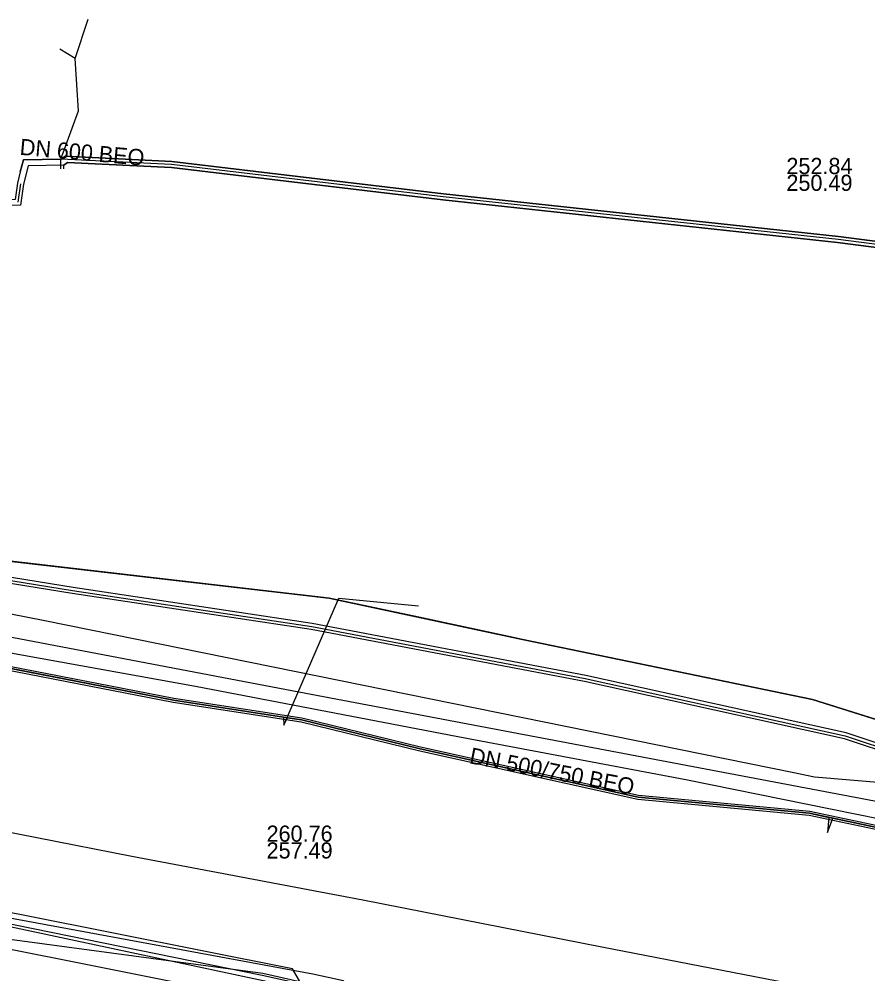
# Model space of a CAD drawing. Extents: x -599951 to -598963, y -1164095 to -1162939.
# Drawn here: x -599823.08 to -599781.05, y -1163059.74 to -1163012.43 of the extents above; entities that cross this region are included whole.
import ezdxf

# ---------------------------------------------------------------- set-up
doc = ezdxf.new("R2010")
doc.units = 0
for name, color, linetype in [('Vrstva 12', 7, 'Continuous'), ('Vrstva 19', 7, 'Continuous'), ('Vrstva 20', 7, 'Continuous'), ('Vrstva 42', 7, 'Continuous'), ('Vrstva 44', 7, 'Continuous'), ('Vrstva 50', 7, 'Continuous'), ('Vrstva 55', 7, 'Continuous'), ('Vrstva 58', 7, 'Continuous')]:
    doc.layers.add(name, color=color, linetype=linetype)

msp = doc.modelspace()

# ---------------------------------------------------------------- linework, layer by layer
at = {"layer": 'Vrstva 12'}
for p, q in [((-599821.8, -1163042.25), (-599823.57, -1163041.9)), ((-599784.71, -1163049.77), (-599821.8, -1163042.25))]:
    msp.add_line(p, q, dxfattribs=at)
for points in [[(-599778.4, -1163050.43), (-599783.7, -1163049.99), (-599784.71, -1163049.77)], [(-599808.4, -1163075.41), (-599806.05, -1163063.47), (-599805.96, -1163062.96), (-599805.85, -1163062.25), (-599805.95, -1163061.63), (-599806.18, -1163061.15), (-599806.36, -1163060.78), (-599806.57, -1163060.51), (-599807.02, -1163060.09), (-599808.54, -1163059.75), (-599841.96, -1163053.57), (-599846.49, -1163052.73)]]:
    msp.add_lwpolyline(points, dxfattribs=at)
at = {"layer": 'Vrstva 19'}
msp.add_lwpolyline([(-599741.561, -1163083.741), (-599749.337, -1163082.368), (-599759.986, -1163080.568), (-599773.585, -1163078.162), (-599785.969, -1163075.634), (-599789.812, -1163076.062), (-599794.62, -1163074.71), (-599796.63, -1163073), (-599800.62, -1163069), (-599804.87, -1163064.7), (-599807.8, -1163061.67), (-599826.41, -1163057.95), (-599839.25, -1163055.38), (-599857.71, -1163051.77), (-599869.416, -1163053.613), (-599869.995, -1163053.663), (-599872.225, -1163054.024), (-599874.316, -1163053.849), (-599875.409, -1163053.774)], dxfattribs=at)
at = {"layer": 'Vrstva 20'}
msp.add_lwpolyline([(-599883.05, -1163052.54), (-599873.56, -1163051.94), (-599873.14, -1163051.47), (-599872.98, -1163049.36), (-599872.6, -1163047.57), (-599869.57, -1163036.17), (-599869.08, -1163035.73), (-599867.99, -1163036.09), (-599863.42, -1163036.97), (-599853.5, -1163038.54), (-599849.37, -1163039.34), (-599847.49, -1163039.61), (-599846.18, -1163040.18), (-599841.31, -1163041.11), (-599828.6, -1163043.61), (-599815.43, -1163046.17), (-599809.1, -1163047.15), (-599803.22, -1163048.59), (-599792.42, -1163050.98), (-599783.94, -1163051.78), (-599774.84, -1163053.7), (-599762.66, -1163055.93), (-599749, -1163058.61), (-599740.93, -1163058.73)], dxfattribs=at)
at = {"layer": 'Vrstva 42'}
for p, q in [((-599826.206, -1163038.978), (-599807.734, -1163041.119)), ((-599826.206, -1163038.978), (-599807.734, -1163041.119)), ((-599807.734, -1163041.119), (-599798.148, -1163043.163)), ((-599807.734, -1163041.119), (-599798.148, -1163043.163)), ((-599798.148, -1163043.163), (-599783.799, -1163046.138)), ((-599798.148, -1163043.163), (-599783.799, -1163046.138)), ((-599783.799, -1163046.138), (-599778.116, -1163047.934)), ((-599783.799, -1163046.138), (-599778.116, -1163047.934))]:
    msp.add_line(p, q, dxfattribs=at)
for points in [[(-599821.016, -1163019.854), (-599821.01, -1163019.37), (-599820.142, -1163016.97), (-599820.3, -1163014.39), (-599819.661, -1163012.431)], [(-599821.016, -1163019.854), (-599821.01, -1163019.37), (-599820.142, -1163016.97), (-599820.3, -1163014.39), (-599819.661, -1163012.431)], [(-599823.02, -1163019.991), (-599822.87, -1163019.4), (-599821.01, -1163019.37), (-599820.142, -1163016.97), (-599820.3, -1163014.39), (-599821.07, -1163013.92)], [(-599823.02, -1163019.991), (-599822.87, -1163019.4), (-599821.01, -1163019.37), (-599820.142, -1163016.97), (-599820.3, -1163014.39), (-599821.07, -1163013.92)], [(-599815.518, -1163019.48), (-599820.791, -1163019.23), (-599821.01, -1163019.37), (-599822.87, -1163019.4), (-599823.02, -1163019.991), (-599823.159, -1163020.568), (-599823.271, -1163021.364), (-599827.714, -1163021.51), (-599835.493, -1163022.702), (-599852.557, -1163025.328), (-599854.173, -1163026.768), (-599855.063, -1163030.103), (-599854.618, -1163032.62), (-599851.529, -1163035.218), (-599847.993, -1163036.016), (-599847.84, -1163036.05), (-599848.693, -1163040.788), (-599851.012, -1163052.737), (-599851.441, -1163055.21), (-599851.947, -1163060.521), (-599893.107, -1163090.941)], [(-599815.518, -1163019.48), (-599820.791, -1163019.23), (-599821.01, -1163019.37), (-599822.87, -1163019.4), (-599823.02, -1163019.991), (-599823.159, -1163020.568), (-599823.271, -1163021.364), (-599827.714, -1163021.51), (-599835.493, -1163022.702), (-599852.557, -1163025.328), (-599854.173, -1163026.768), (-599855.063, -1163030.103), (-599854.618, -1163032.62), (-599851.529, -1163035.218), (-599847.993, -1163036.016), (-599847.84, -1163036.05), (-599848.693, -1163040.788), (-599851.012, -1163052.737), (-599851.441, -1163055.21), (-599851.947, -1163060.521), (-599893.107, -1163090.941)], [(-599735.209, -1163031.191), (-599748.973, -1163028.922), (-599754.582, -1163027.773), (-599763.609, -1163026.245), (-599763.605, -1163026.246), (-599764.382, -1163026.091), (-599764.757, -1163025.994), (-599772.386, -1163024.512), (-599782.512, -1163023.201), (-599802.063, -1163021.081), (-599815.518, -1163019.48), (-599820.791, -1163019.23), (-599821.01, -1163019.37), (-599822.87, -1163019.4), (-599823.02, -1163019.991), (-599823.159, -1163020.568)], [(-599735.209, -1163031.191), (-599748.973, -1163028.922), (-599754.582, -1163027.773), (-599763.609, -1163026.245), (-599763.605, -1163026.246), (-599764.382, -1163026.091), (-599764.757, -1163025.994), (-599772.386, -1163024.512), (-599782.512, -1163023.201), (-599802.063, -1163021.081), (-599815.518, -1163019.48), (-599820.791, -1163019.23), (-599821.01, -1163019.37), (-599822.87, -1163019.4), (-599823.02, -1163019.991), (-599823.159, -1163020.568)], [(-599823.02, -1163019.991), (-599822.87, -1163019.4), (-599821.01, -1163019.37), (-599820.791, -1163019.23), (-599815.518, -1163019.48), (-599802.063, -1163021.081), (-599782.512, -1163023.201), (-599772.386, -1163024.512), (-599764.757, -1163025.994), (-599764.382, -1163026.091), (-599763.605, -1163026.246), (-599763.609, -1163026.245), (-599754.582, -1163027.773), (-599748.973, -1163028.922), (-599735.209, -1163031.191)], [(-599823.02, -1163019.991), (-599822.87, -1163019.4), (-599821.01, -1163019.37), (-599820.791, -1163019.23), (-599815.518, -1163019.48), (-599802.063, -1163021.081), (-599782.512, -1163023.201), (-599772.386, -1163024.512), (-599764.757, -1163025.994), (-599764.382, -1163026.091), (-599763.605, -1163026.246), (-599763.609, -1163026.245), (-599754.582, -1163027.773), (-599748.973, -1163028.922), (-599735.209, -1163031.191)], [(-599735.209, -1163031.191), (-599748.973, -1163028.922), (-599754.582, -1163027.773), (-599763.609, -1163026.245), (-599763.605, -1163026.246), (-599764.382, -1163026.091), (-599764.757, -1163025.994), (-599772.386, -1163024.512), (-599782.512, -1163023.201), (-599802.063, -1163021.081), (-599815.518, -1163019.48), (-599820.791, -1163019.23), (-599821.01, -1163019.37), (-599822.87, -1163019.4), (-599823.02, -1163019.991)], [(-599823.02, -1163019.991), (-599822.87, -1163019.4), (-599821.01, -1163019.37), (-599820.791, -1163019.23), (-599815.518, -1163019.48), (-599802.063, -1163021.081), (-599782.512, -1163023.201), (-599772.386, -1163024.512), (-599764.757, -1163025.994), (-599764.382, -1163026.091), (-599763.605, -1163026.246), (-599763.609, -1163026.245), (-599754.582, -1163027.773), (-599748.973, -1163028.922), (-599735.209, -1163031.191)], [(-599821.01, -1163019.37), (-599822.87, -1163019.4), (-599823.02, -1163019.991)], [(-599763.634, -1163026.393), (-599764.416, -1163026.237), (-599764.79, -1163026.14), (-599772.41, -1163024.66), (-599782.53, -1163023.35), (-599802.08, -1163021.23), (-599815.53, -1163019.63), (-599821.01, -1163019.37)], [(-599735.259, -1163031.487), (-599749.027, -1163029.218), (-599754.638, -1163028.067), (-599763.659, -1163026.541), (-599763.663, -1163026.54), (-599764.45, -1163026.383), (-599764.823, -1163026.286), (-599772.434, -1163024.808), (-599782.548, -1163023.499), (-599802.097, -1163021.379), (-599815.542, -1163019.78), (-599820.691, -1163019.536), (-599820.864, -1163019.668), (-599822.636, -1163019.696), (-599822.861, -1163020.61), (-599823.009, -1163021.656), (-599827.686, -1163021.81)], [(-599735.259, -1163031.487), (-599749.027, -1163029.218), (-599754.638, -1163028.067), (-599763.659, -1163026.541), (-599763.663, -1163026.54), (-599764.45, -1163026.383), (-599764.823, -1163026.286), (-599772.434, -1163024.808), (-599782.548, -1163023.499), (-599802.097, -1163021.379), (-599815.542, -1163019.78), (-599820.691, -1163019.536), (-599820.864, -1163019.668), (-599822.636, -1163019.696), (-599822.861, -1163020.61), (-599823.009, -1163021.656), (-599827.686, -1163021.81)], [(-599820.866, -1163019.856), (-599820.864, -1163019.668), (-599820.691, -1163019.536), (-599815.542, -1163019.78), (-599802.097, -1163021.379), (-599782.548, -1163023.499), (-599772.434, -1163024.808), (-599764.823, -1163026.286), (-599764.45, -1163026.383), (-599763.663, -1163026.54), (-599763.659, -1163026.541), (-599754.638, -1163028.067), (-599749.027, -1163029.218), (-599735.259, -1163031.487)], [(-599820.866, -1163019.856), (-599820.864, -1163019.668), (-599820.691, -1163019.536), (-599815.542, -1163019.78), (-599802.097, -1163021.379), (-599782.548, -1163023.499), (-599772.434, -1163024.808), (-599764.823, -1163026.286), (-599764.45, -1163026.383), (-599763.663, -1163026.54), (-599763.659, -1163026.541), (-599754.638, -1163028.067), (-599749.027, -1163029.218), (-599735.259, -1163031.487)], [(-599735.209, -1163031.191), (-599748.973, -1163028.922), (-599754.582, -1163027.773), (-599763.609, -1163026.245), (-599763.605, -1163026.246), (-599764.382, -1163026.091), (-599764.757, -1163025.994), (-599772.386, -1163024.512), (-599782.512, -1163023.201), (-599802.063, -1163021.081), (-599815.518, -1163019.48)], [(-599735.209, -1163031.191), (-599748.973, -1163028.922), (-599754.582, -1163027.773), (-599763.609, -1163026.245), (-599763.605, -1163026.246), (-599764.382, -1163026.091), (-599764.757, -1163025.994), (-599772.386, -1163024.512), (-599782.512, -1163023.201), (-599802.063, -1163021.081), (-599815.518, -1163019.48)], [(-599823.01, -1163020.589), (-599823.14, -1163021.51)], [(-599736.94, -1163069.5), (-599747.67, -1163067.47), (-599759.18, -1163065.22), (-599771.56, -1163062.81), (-599782.31, -1163060.73), (-599794.22, -1163058.42), (-599806.06, -1163056.09), (-599817.5, -1163053.92), (-599826.93, -1163052.08), (-599837.11, -1163050.1), (-599848.95, -1163047.79), (-599860.32, -1163045.57), (-599870.33, -1163043.62), (-599881.88, -1163041.35), (-599892.48, -1163039.26), (-599902.25, -1163037.36), (-599911.67, -1163035.55), (-599921.63, -1163033.57), (-599932.53, -1163031.46), (-599941.74, -1163029.67), (-599951.125, -1163027.795)], [(-599742.215, -1163055.552), (-599755.449, -1163053.841), (-599771.375, -1163051.364), (-599782.13, -1163047.795), (-599795.02, -1163044.953), (-599808.565, -1163042.372), (-599820.407, -1163040.592), (-599840.692, -1163037.303), (-599847.928, -1163035.723), (-599848.08, -1163035.69), (-599848.987, -1163040.732), (-599851.308, -1163052.683), (-599851.739, -1163055.17), (-599852.233, -1163060.359), (-599893.313, -1163090.719), (-599898.373, -1163096.584), (-599905.793, -1163118.694), (-599909.483, -1163130.424), (-599919.431, -1163160.679), (-599923.942, -1163172.071), (-599928.754, -1163188.287), (-599951.125, -1163246.248)], [(-599742.215, -1163055.552), (-599755.449, -1163053.841), (-599771.375, -1163051.364), (-599782.13, -1163047.795), (-599795.02, -1163044.953), (-599808.565, -1163042.372), (-599820.407, -1163040.592), (-599840.692, -1163037.303), (-599847.928, -1163035.723), (-599848.08, -1163035.69), (-599848.987, -1163040.732), (-599851.308, -1163052.683), (-599851.739, -1163055.17), (-599852.233, -1163060.359), (-599893.313, -1163090.719), (-599898.373, -1163096.584), (-599905.793, -1163118.694), (-599909.483, -1163130.424), (-599919.431, -1163160.679), (-599923.942, -1163172.071), (-599928.754, -1163188.287), (-599951.125, -1163246.248)], [(-599847.96, -1163035.87), (-599840.72, -1163037.45), (-599820.43, -1163040.74), (-599808.59, -1163042.52), (-599795.05, -1163045.1), (-599782.17, -1163047.94), (-599771.41, -1163051.51), (-599755.47, -1163053.99), (-599742.24, -1163055.7), (-599730.83, -1163058.1), (-599723.97, -1163059.15), (-599715.25, -1163060.7), (-599698.74, -1163063.9), (-599666.16, -1163068.57), (-599655.17, -1163067.91), (-599647.96, -1163067.11), (-599641.24, -1163065.92), (-599633.17, -1163063.6), (-599622.92, -1163059.72), (-599616.64, -1163055.22), (-599609.94, -1163050.49)], [(-599742.265, -1163055.848), (-599755.491, -1163054.139), (-599771.445, -1163051.656), (-599782.21, -1163048.085), (-599795.08, -1163045.247), (-599808.615, -1163042.668), (-599820.453, -1163040.888), (-599840.748, -1163037.597), (-599847.84, -1163036.05), (-599848.693, -1163040.788), (-599851.012, -1163052.737), (-599851.441, -1163055.21), (-599851.947, -1163060.521), (-599893.107, -1163090.941), (-599898.107, -1163096.736), (-599905.507, -1163118.786), (-599909.197, -1163130.516), (-599919.149, -1163160.781), (-599923.658, -1163172.169), (-599928.466, -1163188.373), (-599951.125, -1163247.074)], [(-599742.265, -1163055.848), (-599755.491, -1163054.139), (-599771.445, -1163051.656), (-599782.21, -1163048.085), (-599795.08, -1163045.247), (-599808.615, -1163042.668), (-599820.453, -1163040.888), (-599840.748, -1163037.597), (-599847.84, -1163036.05), (-599848.693, -1163040.788), (-599851.012, -1163052.737), (-599851.441, -1163055.21), (-599851.947, -1163060.521), (-599893.107, -1163090.941), (-599898.107, -1163096.736), (-599905.507, -1163118.786), (-599909.197, -1163130.516), (-599919.149, -1163160.781), (-599923.658, -1163172.169), (-599928.466, -1163188.373), (-599951.125, -1163247.074)], [(-599790.25, -1163100.41), (-599791.97, -1163097.44), (-599790.35, -1163085.48), (-599790.7, -1163085.03), (-599800.21, -1163083.2), (-599802.06, -1163082.74), (-599802.3, -1163082.3), (-599802.03, -1163079.98), (-599800.42, -1163070.73), (-599800.55, -1163070.2), (-599806.83, -1163069.05), (-599807.31, -1163068.48), (-599807.69, -1163063.21), (-599807.82, -1163062.44), (-599809.55, -1163059.49), (-599822.79, -1163056.85), (-599830.99, -1163055.24)]]:
    msp.add_lwpolyline(points, dxfattribs=at)
at = {"layer": 'Vrstva 44'}
msp.add_lwpolyline([(-599951.125, -1163018.319), (-599947.551, -1163019.333), (-599942.738, -1163020.646), (-599932.806, -1163022.793), (-599910.515, -1163027.389), (-599898.233, -1163029.739), (-599885.727, -1163032.363), (-599873.009, -1163034.84), (-599861.264, -1163036.995), (-599853.19, -1163038.533), (-599847.084, -1163039.492), (-599839.909, -1163041.111), (-599824.895, -1163043.577), (-599814.349, -1163045.484), (-599801.363, -1163047.973), (-599790.063, -1163050.107), (-599778.01, -1163052.554), (-599760.155, -1163055.725), (-599748.035, -1163058.372), (-599724.432, -1163062.801)], dxfattribs=at)
at = {"layer": 'Vrstva 50'}
msp.add_lwpolyline([(-599740.93, -1163058.73), (-599749, -1163058.61), (-599762.66, -1163055.93), (-599774.84, -1163053.7), (-599782.792, -1163052.031), (-599783.94, -1163051.78), (-599792.42, -1163050.98), (-599803.22, -1163048.59), (-599809.1, -1163047.15), (-599809.988, -1163047.015), (-599815.43, -1163046.17), (-599843.958, -1163040.613)], dxfattribs=at)
at = {"layer": 'Vrstva 55'}
for points in [[(-599664.02, -1163109.18), (-599663.75, -1163108.82), (-599661.75, -1163109.07), (-599658.99, -1163095.65), (-599655.61, -1163093.65), (-599653.6, -1163094.02), (-599652.97, -1163091.01), (-599676.92, -1163086.63), (-599680.55, -1163086.75), (-599712.65, -1163080.11), (-599750.51, -1163072.96), (-599770.19, -1163068.95), (-599811.009, -1163059.716), (-599833.75, -1163056.67), (-599858.82, -1163052.03), (-599858.7, -1163050.9), (-599897.68, -1163043.25), (-599927.27, -1163037.74), (-599948.58, -1163035.1), (-599951.125, -1163035.045)], [(-599664.02, -1163109.18), (-599663.73, -1163108.63), (-599661.59, -1163109.02), (-599659.06, -1163095.58), (-599655.95, -1163093.64), (-599653.8, -1163094.03), (-599652.83, -1163091.3), (-599676.97, -1163086.63), (-599680.67, -1163086.82), (-599708.89, -1163080.98), (-599759.5, -1163071.06), (-599842.375, -1163053.387), (-599858.58, -1163051.98), (-599858.78, -1163050.81), (-599893.42, -1163044), (-599928.85, -1163037.58), (-599938.78, -1163036.41), (-599941.11, -1163043.03), (-599943.478, -1163048.564)], [(-599846.18, -1163040.18), (-599815.43, -1163046.17), (-599809.988, -1163047.015), (-599809.97, -1163047.41), (-599809.79, -1163047.045), (-599809.1, -1163047.15), (-599803.22, -1163048.59), (-599792.42, -1163050.98), (-599783.94, -1163051.78), (-599782.988, -1163051.989), (-599783.05, -1163052.73), (-599782.792, -1163052.031), (-599774.84, -1163053.7), (-599762.66, -1163055.93), (-599753.51, -1163057.73), (-599753.62, -1163058.34)], [(-599809.97, -1163047.41), (-599807.25, -1163041.12), (-599803.3, -1163041.51)], [(-599711.23, -1163080.4), (-599759.11, -1163071.25), (-599811.043, -1163059.819), (-599842.409, -1163053.422), (-599858, -1163051.98), (-599858.97, -1163051.79), (-599858.78, -1163050.81), (-599893.42, -1163044), (-599896.93, -1163051.01), (-599905.105, -1163053.383), (-599913.454, -1163056.211), (-599913.92, -1163056.19), (-599917.22, -1163057.25), (-599922.701, -1163059.24), (-599920.87, -1163063.66), (-599928.88, -1163069.16), (-599943.308, -1163079.607), (-599947.254, -1163081.556), (-599951.125, -1163083.176)]]:
    msp.add_lwpolyline(points, dxfattribs=at)
at = {"layer": 'Vrstva 58'}
for points in [[(-599951.125, -1163017.951), (-599942.396, -1163020.445), (-599928.216, -1163023.175), (-599909.436, -1163026.875), (-599898.216, -1163029.295), (-599876.466, -1163033.695), (-599839.596, -1163041.095), (-599823.356, -1163043.075), (-599809.226, -1163045.765), (-599771.136, -1163052.985), (-599752.946, -1163056.655), (-599739.506, -1163059.075)], [(-599951.125, -1163017.951), (-599942.396, -1163020.445), (-599928.216, -1163023.175), (-599909.436, -1163026.875), (-599898.216, -1163029.295), (-599876.466, -1163033.695), (-599839.596, -1163041.095), (-599823.356, -1163043.075), (-599809.226, -1163045.765), (-599771.136, -1163052.985), (-599752.946, -1163056.655), (-599739.506, -1163059.075)], [(-599895.104, -1163026.704), (-599877.002, -1163030.363), (-599865.209, -1163032.412), (-599856.59, -1163034.344), (-599852.059, -1163034.673), (-599843.593, -1163035.7), (-599839.077, -1163036.896), (-599826.206, -1163038.978), (-599807.734, -1163041.119), (-599798.148, -1163043.163), (-599783.799, -1163046.138), (-599778.116, -1163047.934), (-599767.984, -1163049.822), (-599757.25, -1163051.301), (-599755.861, -1163052.095), (-599756.19, -1163053.12), (-599756.43, -1163053.89), (-599756.84, -1163055.76), (-599757.116, -1163057.018), (-599762.66, -1163055.93)], [(-599895.104, -1163026.704), (-599877.002, -1163030.363), (-599865.209, -1163032.412), (-599856.59, -1163034.344), (-599852.059, -1163034.673), (-599843.593, -1163035.7), (-599839.077, -1163036.896), (-599826.206, -1163038.978), (-599807.734, -1163041.119), (-599798.148, -1163043.163), (-599783.799, -1163046.138), (-599778.116, -1163047.934), (-599767.984, -1163049.822), (-599757.25, -1163051.301), (-599755.861, -1163052.095), (-599756.19, -1163053.12), (-599756.43, -1163053.89), (-599756.84, -1163055.76), (-599757.116, -1163057.018), (-599762.66, -1163055.93)], [(-599895.104, -1163026.704), (-599877.002, -1163030.363), (-599865.209, -1163032.412), (-599856.59, -1163034.344), (-599852.059, -1163034.673), (-599843.593, -1163035.7), (-599839.077, -1163036.896), (-599826.206, -1163038.978), (-599807.734, -1163041.119), (-599798.148, -1163043.163), (-599783.799, -1163046.138), (-599778.116, -1163047.934), (-599767.984, -1163049.822), (-599757.25, -1163051.301), (-599755.861, -1163052.095), (-599756.19, -1163053.12), (-599756.43, -1163053.89), (-599756.84, -1163055.76), (-599757.116, -1163057.018), (-599762.66, -1163055.93)], [(-599869.54, -1163034.95), (-599867.965, -1163035.993), (-599863.403, -1163036.871), (-599853.483, -1163038.441), (-599849.353, -1163039.241), (-599847.462, -1163039.513), (-599846.15, -1163040.084), (-599841.291, -1163041.012), (-599828.581, -1163043.512), (-599815.413, -1163046.071), (-599809.08, -1163047.052), (-599803.197, -1163048.493), (-599792.404, -1163050.881), (-599783.925, -1163051.681), (-599774.821, -1163053.602), (-599762.641, -1163055.832), (-599748.99, -1163058.51), (-599740.918, -1163058.63)], [(-599762.66, -1163055.93), (-599772.176, -1163054.188), (-599774.84, -1163053.7), (-599783.94, -1163051.78), (-599792.42, -1163050.98), (-599803.22, -1163048.59), (-599809.1, -1163047.15), (-599809.988, -1163047.015), (-599815.43, -1163046.17), (-599843.958, -1163040.613), (-599846.18, -1163040.18), (-599847.49, -1163039.61), (-599849.37, -1163039.34), (-599854.299, -1163038.414), (-599863.42, -1163036.97), (-599867.99, -1163036.09), (-599869.08, -1163035.73), (-599869.57, -1163036.17), (-599872.613, -1163047.558), (-599872.98, -1163049.36), (-599873.14, -1163051.47), (-599873.56, -1163051.94), (-599883.05, -1163052.54)], [(-599762.66, -1163055.93), (-599772.176, -1163054.188), (-599774.84, -1163053.7), (-599783.94, -1163051.78), (-599792.42, -1163050.98), (-599803.22, -1163048.59), (-599809.1, -1163047.15), (-599809.988, -1163047.015), (-599815.43, -1163046.17), (-599843.958, -1163040.613), (-599846.18, -1163040.18), (-599847.49, -1163039.61), (-599849.37, -1163039.34), (-599854.299, -1163038.414), (-599863.42, -1163036.97), (-599867.99, -1163036.09), (-599869.08, -1163035.73), (-599869.57, -1163036.17), (-599872.613, -1163047.558), (-599872.98, -1163049.36), (-599873.14, -1163051.47), (-599873.56, -1163051.94), (-599883.05, -1163052.54)], [(-599762.66, -1163055.93), (-599772.176, -1163054.188), (-599774.84, -1163053.7), (-599783.94, -1163051.78), (-599792.42, -1163050.98), (-599803.22, -1163048.59), (-599809.1, -1163047.15), (-599809.988, -1163047.015), (-599815.43, -1163046.17), (-599843.958, -1163040.613), (-599846.18, -1163040.18), (-599847.49, -1163039.61), (-599849.37, -1163039.34), (-599854.299, -1163038.414), (-599863.42, -1163036.97), (-599867.99, -1163036.09), (-599869.08, -1163035.73), (-599869.57, -1163036.17), (-599872.613, -1163047.558), (-599872.98, -1163049.36), (-599873.14, -1163051.47), (-599873.56, -1163051.94), (-599883.05, -1163052.54)], [(-599883.05, -1163052.54), (-599873.56, -1163051.94), (-599873.14, -1163051.47), (-599872.98, -1163049.36), (-599872.6, -1163047.57), (-599869.57, -1163036.17), (-599869.08, -1163035.73), (-599868.015, -1163036.187), (-599863.437, -1163037.069), (-599853.517, -1163038.639), (-599849.387, -1163039.439), (-599847.518, -1163039.707), (-599846.21, -1163040.276), (-599841.329, -1163041.208), (-599828.619, -1163043.708), (-599815.447, -1163046.269), (-599809.12, -1163047.248), (-599803.243, -1163048.687), (-599792.436, -1163051.079), (-599783.955, -1163051.879)], [(-599883.05, -1163052.54), (-599873.56, -1163051.94), (-599873.14, -1163051.47), (-599872.98, -1163049.36), (-599872.6, -1163047.57), (-599869.57, -1163036.17), (-599869.08, -1163035.73), (-599868.015, -1163036.187), (-599863.437, -1163037.069), (-599853.517, -1163038.639), (-599849.387, -1163039.439), (-599847.518, -1163039.707), (-599846.21, -1163040.276), (-599841.329, -1163041.208), (-599828.619, -1163043.708), (-599815.447, -1163046.269), (-599809.12, -1163047.248), (-599803.243, -1163048.687), (-599792.436, -1163051.079), (-599783.955, -1163051.879)], [(-599843.958, -1163040.613), (-599815.43, -1163046.17), (-599809.988, -1163047.015), (-599809.1, -1163047.15), (-599803.22, -1163048.59), (-599792.42, -1163050.98), (-599783.94, -1163051.78), (-599774.84, -1163053.7), (-599772.176, -1163054.188), (-599762.66, -1163055.93), (-599757.116, -1163057.018), (-599756.84, -1163055.76), (-599756.43, -1163053.89), (-599756.19, -1163053.12), (-599755.861, -1163052.095), (-599757.25, -1163051.301), (-599767.984, -1163049.822), (-599778.116, -1163047.934), (-599783.799, -1163046.138), (-599798.148, -1163043.163), (-599807.734, -1163041.119), (-599826.206, -1163038.978)], [(-599843.958, -1163040.613), (-599815.43, -1163046.17), (-599809.988, -1163047.015), (-599809.1, -1163047.15), (-599803.22, -1163048.59), (-599792.42, -1163050.98), (-599783.94, -1163051.78), (-599774.84, -1163053.7), (-599772.176, -1163054.188), (-599762.66, -1163055.93), (-599757.116, -1163057.018), (-599756.84, -1163055.76), (-599756.43, -1163053.89), (-599756.19, -1163053.12), (-599755.861, -1163052.095), (-599757.25, -1163051.301), (-599767.984, -1163049.822), (-599778.116, -1163047.934), (-599783.799, -1163046.138), (-599798.148, -1163043.163), (-599807.734, -1163041.119), (-599826.206, -1163038.978)], [(-599843.958, -1163040.613), (-599815.43, -1163046.17), (-599809.988, -1163047.015), (-599809.1, -1163047.15), (-599803.22, -1163048.59), (-599792.42, -1163050.98), (-599783.94, -1163051.78), (-599774.84, -1163053.7), (-599772.176, -1163054.188), (-599762.66, -1163055.93), (-599757.116, -1163057.018), (-599756.84, -1163055.76), (-599756.43, -1163053.89), (-599756.19, -1163053.12), (-599755.861, -1163052.095), (-599757.25, -1163051.301), (-599767.984, -1163049.822), (-599778.116, -1163047.934), (-599783.799, -1163046.138), (-599798.148, -1163043.163), (-599807.734, -1163041.119), (-599826.206, -1163038.978)], [(-599740.93, -1163058.73), (-599749, -1163058.61), (-599757.116, -1163057.018), (-599756.84, -1163055.76), (-599756.43, -1163053.89), (-599756.307, -1163053.495), (-599756.188, -1163053.113), (-599755.861, -1163052.095), (-599757.25, -1163051.301), (-599759.361, -1163051.01), (-599764.528, -1163050.298), (-599767.984, -1163049.822), (-599778.116, -1163047.934), (-599779.105, -1163047.622), (-599783.799, -1163046.138), (-599798.148, -1163043.163), (-599798.593, -1163043.068), (-599803.287, -1163042.067), (-599807.734, -1163041.119), (-599826.206, -1163038.978)], [(-599783.955, -1163051.879), (-599774.859, -1163053.798), (-599762.679, -1163056.028), (-599749.01, -1163058.71), (-599740.942, -1163058.83)], [(-599783.955, -1163051.879), (-599774.859, -1163053.798), (-599762.679, -1163056.028), (-599749.01, -1163058.71), (-599740.942, -1163058.83)]]:
    msp.add_lwpolyline(points, dxfattribs=at)

# ---------------------------------------------------------------- texts
at = {"layer": 'Vrstva 12'}
for s, rotation, p in [('DN 600 BEO', 354.9207, (-599823.073, -1163019.151)), ('DN 500/750 BEO', 349.0459, (-599800.819, -1163049.299))]:
    msp.add_text(s, height=0.8, rotation=rotation, dxfattribs=at).set_placement(p)
for s, p in [('252.84', (-599785.085, -1163020.109)), ('250.49', (-599785.085, -1163020.941)), ('260.76', (-599810.827, -1163053.19)), ('257.49', (-599810.827, -1163054.022))]:
    msp.add_text(s, height=0.8, dxfattribs=at).set_placement(p)

doc.saveas('drawing.dxf')
